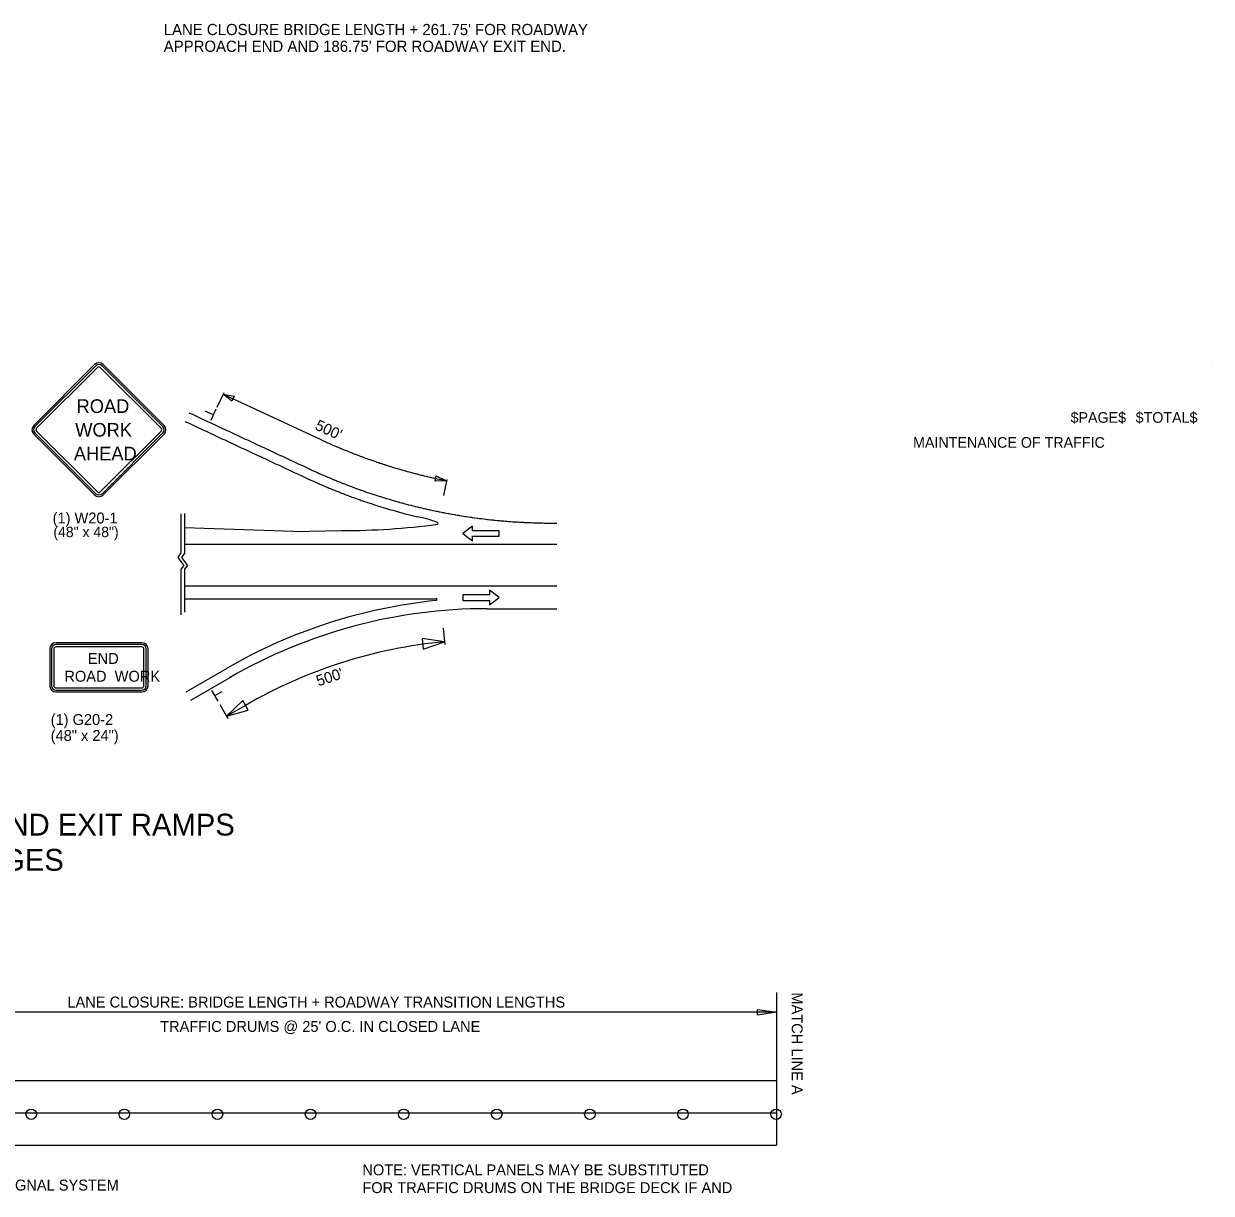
# Model space of a CAD drawing. Extents: x 1930579 to 1939784, y 596179 to 597522.
# Drawn here: x 1938290 to 1938942, y 596879 to 597522 of the extents above; entities that cross this region are included whole.
import ezdxf

# ---------------------------------------------------------------- set-up
doc = ezdxf.new("R2010")
doc.units = 0
for name, color, linetype in [('Default', 7, 'Continuous'), ('P_TC_Signs_Temporary', 7, 'Continuous'), ('R_Annotation', 7, 'Continuous'), ('R_Border', 7, 'Continuous'), ('R_Striping', 7, 'Continuous'), ('S_EDGE_PAVEMENT', 7, 'Continuous'), ('S_SHOULDER', 7, 'Continuous')]:
    doc.layers.add(name, color=color, linetype=linetype)

msp = doc.modelspace()

# ---------------------------------------------------------------- linework, layer by layer
at = {"layer": 'Default'}
for p, q in [((1938399.49, 597319.21), (1938395.68, 597311.05)), ((1938393.76, 597307.15), (1938389.58, 597309.1)), ((1938395.26, 597310.15), (1938392.41, 597304.03)), ((1938522.05, 597271.64), (1938520.29, 597262.81)), ((1938520.16, 597189.93), (1938520.95, 597180.97)), ((1938392.83, 597155.7), (1938396.21, 597149.85)), ((1938394.6, 597152.84), (1938398.59, 597155.14)), ((1938397.32, 597148), (1938401.82, 597140.2)), ((1938411.46, 597147.5), (1938401.07, 597141.5)), ((1938703.26, 596989.79), (1938703.26, 596905.9)), ((1938703.26, 596978.92), (1938258.87, 596978.92)), ((1938692.72, 596977.33), (1938692.72, 596980.49)), ((1938692.72, 596980.49), (1938703.26, 596978.92)), ((1938703.26, 596978.92), (1938692.72, 596977.33)), ((1937601.26, 596941.48), (1938703.26, 596941.48)), ((1937499.1, 596923.69), (1938703.26, 596923.69)), ((1937601.26, 596905.9), (1938703.26, 596905.9))]:
    msp.add_line(p, q, dxfattribs=at)
for points in [[(1938399.17, 597318.53), (1938452.49, 597293.67), (1938452.96, 597293.45), (1938454.06, 597292.94), (1938454.06, 597292.94), (1938455.15, 597292.44), (1938455.64, 597292.22), (1938456.24, 597291.95), (1938457.23, 597291.5), (1938457.34, 597291.46), (1938458.45, 597290.96), (1938458.81, 597290.81), (1938459.54, 597290.48), (1938460.4, 597290.11), (1938460.64, 597290.01), (1938461.76, 597289.53), (1938461.99, 597289.43), (1938462.86, 597289.06), (1938463.59, 597288.75), (1938463.93, 597288.61), (1938463.96, 597288.6), (1938465.09, 597288.13), (1938465.18, 597288.09), (1938466.2, 597287.68), (1938466.79, 597287.43), (1938467.31, 597287.23), (1938468.41, 597286.78), (1938468.42, 597286.78), (1938469.07, 597286.52), (1938469.55, 597286.33), (1938470.01, 597286.15), (1938470.66, 597285.89), (1938471.64, 597285.52), (1938471.78, 597285.46), (1938472.92, 597285.03), (1938473.25, 597284.9), (1938474.04, 597284.6), (1938474.88, 597284.29), (1938475.16, 597284.18), (1938476.3, 597283.76), (1938476.49, 597283.69), (1938477.43, 597283.35), (1938478.13, 597283.09), (1938478.55, 597282.94), (1938479.7, 597282.53), (1938479.75, 597282.51), (1938480.83, 597282.14), (1938481.4, 597281.94), (1938481.96, 597281.74), (1938483.04, 597281.37), (1938483.09, 597281.35), (1938484.24, 597280.96), (1938484.68, 597280.82), (1938485.38, 597280.58), (1938486.33, 597280.27), (1938486.52, 597280.21), (1938487.67, 597279.83), (1938487.97, 597279.74), (1938488.81, 597279.47), (1938489.63, 597279.21), (1938489.95, 597279.1), (1938491.12, 597278.74), (1938491.27, 597278.69), (1938492.26, 597278.39), (1938492.94, 597278.18), (1938493.41, 597278.04), (1938494.57, 597277.69), (1938494.59, 597277.68), (1938495.72, 597277.35), (1938496.26, 597277.19), (1938496.87, 597277.02), (1938497.93, 597276.71), (1938498.02, 597276.68), (1938499.19, 597276.35), (1938499.59, 597276.24), (1938500.34, 597276.03), (1938501.27, 597275.78), (1938501.5, 597275.72), (1938502.67, 597275.4), (1938502.93, 597275.33), (1938503.83, 597275.09), (1938504.62, 597274.88), (1938504.99, 597274.79), (1938506.17, 597274.48), (1938506.29, 597274.45), (1938507.33, 597274.19), (1938507.98, 597274.03), (1938508.49, 597273.9), (1938509.66, 597273.61), (1938510.84, 597273.33), (1938511.34, 597273.21), (1938512, 597273.06), (1938513.04, 597272.81), (1938513.18, 597272.78), (1938513.43, 597272.72), (1938514.35, 597272.51), (1938514.53, 597272.47), (1938514.72, 597272.43), (1938515.52, 597272.25), (1938516.42, 597272.05), (1938516.69, 597271.99), (1938517.88, 597271.74), (1938518.11, 597271.69), (1938519.05, 597271.49), (1938519.81, 597271.33), (1938520.23, 597271.24), (1938521.42, 597271), (1938521.5, 597270.98), (1938521.73, 597270.94), (1938521.73, 597270.94), (1938521.9, 597270.9)], [(1938376.02, 597252.77), (1938376.02, 597231.25), (1938374.36, 597228.78), (1938377.59, 597224.35), (1938375.89, 597222.3), (1938375.88, 597197.28)], [(1938378.06, 597252.97), (1938378.06, 597231.16), (1938376.4, 597228.69), (1938379.64, 597224.26), (1938377.93, 597222.22), (1938377.93, 597198.72)]]:
    msp.add_lwpolyline(points, dxfattribs=at)
for points in [[(1938403.98, 597314.63), (1938399.17, 597318.53), (1938405.24, 597317.35)], [(1938516.32, 597273.55), (1938521.91, 597270.9), (1938515.73, 597270.6)], [(1938509.16, 597178.33), (1938520.82, 597182.46), (1938508.59, 597184.31)], [(1938409.96, 597150.1), (1938401.07, 597141.5), (1938412.96, 597144.9)]]:
    msp.add_lwpolyline(points, close=True, dxfattribs=at)
for centre in [(1938293.74, 596922.85), (1938344.9, 596922.85), (1938396.07, 596922.85), (1938447.23, 596922.85), (1938498.39, 596922.85), (1938549.55, 596922.85), (1938600.72, 596922.85), (1938651.88, 596922.85), (1938703.04, 596922.85)]:
    msp.add_circle(centre, 2.88, dxfattribs=at)
msp.add_arc((1938546.51, 596913.58), 270.11, 95.458, 120.00001, dxfattribs=at)
at = {"layer": 'P_TC_Signs_Temporary'}
for p, q in [((1938295.13, 597301.29), (1938328.54, 597334.71)), ((1938295.79, 597300.63), (1938329.2, 597334.04)), ((1938296.72, 597299.7), (1938330.13, 597333.11)), ((1938331.72, 597333.11), (1938365.13, 597299.7)), ((1938332.65, 597334.04), (1938366.06, 597300.63)), ((1938333.31, 597334.71), (1938366.72, 597301.29)), ((1938330.13, 597264.7), (1938296.72, 597298.11)), ((1938365.13, 597298.11), (1938331.72, 597264.7)), ((1938328.54, 597263.11), (1938295.13, 597296.52)), ((1938329.2, 597263.77), (1938295.79, 597297.18)), ((1938366.06, 597297.18), (1938332.65, 597263.77)), ((1938366.72, 597296.52), (1938333.31, 597263.11)), ((1938354.55, 597181.86), (1938307.3, 597181.86)), ((1938354.55, 597180.92), (1938307.3, 597180.92)), ((1938303.92, 597178.48), (1938303.92, 597158.23)), ((1938304.86, 597178.48), (1938304.86, 597158.23)), ((1938306.17, 597178.48), (1938306.17, 597158.23)), ((1938354.55, 597179.61), (1938307.3, 597179.61)), ((1938355.67, 597158.23), (1938355.67, 597178.48)), ((1938356.99, 597158.23), (1938356.99, 597178.48)), ((1938357.92, 597158.23), (1938357.92, 597178.48)), ((1938307.3, 597157.11), (1938354.55, 597157.11)), ((1938307.3, 597155.79), (1938354.55, 597155.79)), ((1938307.3, 597154.86), (1938354.55, 597154.86))]:
    msp.add_line(p, q, dxfattribs=at)
for centre, radius, start, end in [((1938330.92, 597332.32), 3.38, 45, 135), ((1938330.92, 597332.32), 2.44, 45, 135), ((1938330.92, 597332.32), 1.13, 45, 135), ((1938297.51, 597298.91), 3.37, 135, 225), ((1938297.51, 597298.91), 2.44, 135, 225), ((1938297.51, 597298.91), 1.12, 135, 225), ((1938364.33, 597298.91), 1.12, 315, 45), ((1938364.33, 597298.91), 2.44, 315, 45), ((1938364.33, 597298.91), 3.38, 315, 45), ((1938330.92, 597265.5), 3.38, 225, 315), ((1938330.92, 597265.5), 2.44, 225, 315), ((1938330.92, 597265.5), 1.13, 225, 315), ((1938307.3, 597178.48), 3.38, 90, 180), ((1938307.3, 597178.48), 2.44, 90, 180), ((1938354.55, 597178.48), 3.38, 360, 90), ((1938354.55, 597178.48), 2.44, 360, 90), ((1938307.3, 597178.48), 1.13, 90, 180), ((1938354.55, 597178.48), 1.13, 360, 90), ((1938307.3, 597158.23), 3.38, 180, 270), ((1938307.3, 597158.23), 2.44, 180, 270), ((1938307.3, 597158.23), 1.13, 180, 270), ((1938354.55, 597158.23), 2.44, 270, 360), ((1938354.55, 597158.23), 1.13, 270, 360), ((1938354.55, 597158.23), 3.38, 270, 360)]:
    msp.add_arc(centre, radius, start, end, dxfattribs=at)
at = {"layer": 'R_Border'}
msp.add_line((1938942.12, 597333.4), (1938942.12, 597333.4), dxfattribs=at)
at = {"layer": 'R_Striping'}
for points in [[(1938536.12, 597245.93), (1938530.93, 597241.93), (1938536.12, 597237.93), (1938536.12, 597240.43), (1938550.83, 597240.43), (1938550.83, 597243.43), (1938536.12, 597243.43)], [(1938545.64, 597202.68), (1938550.83, 597206.68), (1938545.64, 597210.68), (1938545.64, 597208.18), (1938530.93, 597208.18), (1938530.93, 597205.18), (1938545.64, 597205.18)]]:
    msp.add_lwpolyline(points, close=True, dxfattribs=at)
at = {"layer": 'S_EDGE_PAVEMENT'}
for p, q in [((1938437.9, 597243.08), (1938378.06, 597245.08)), ((1938437.9, 597243.08), (1938464.18, 597243.53)), ((1938378.2, 597206.08), (1938516.23, 597206.08))]:
    msp.add_line(p, q, dxfattribs=at)
for points in [[(1938378.29, 597303.45), (1938378.57, 597303.32), (1938379.7, 597302.79), (1938380.83, 597302.26), (1938381.96, 597301.73), (1938383.1, 597301.2), (1938384.23, 597300.68), (1938385.36, 597300.15), (1938386.5, 597299.62), (1938387.63, 597299.09), (1938388.76, 597298.56), (1938389.89, 597298.04), (1938391.03, 597297.51), (1938392.16, 597296.98), (1938393.29, 597296.45), (1938394.43, 597295.92), (1938395.56, 597295.39), (1938396.69, 597294.87), (1938397.83, 597294.34), (1938398.96, 597293.81), (1938400.09, 597293.28), (1938401.22, 597292.75), (1938402.36, 597292.22), (1938403.49, 597291.7), (1938404.62, 597291.17), (1938405.76, 597290.64), (1938406.89, 597290.11), (1938408.02, 597289.58), (1938409.15, 597289.05), (1938410.29, 597288.53), (1938411.42, 597288), (1938412.55, 597287.47), (1938413.69, 597286.94), (1938414.82, 597286.41), (1938415.95, 597285.88), (1938417.08, 597285.36), (1938418.22, 597284.83), (1938419.35, 597284.3), (1938420.48, 597283.77), (1938421.62, 597283.24), (1938421.68, 597283.21), (1938422.75, 597282.72), (1938423.88, 597282.19), (1938425.01, 597281.66), (1938425.83, 597281.28), (1938426.15, 597281.13), (1938427.28, 597280.6), (1938428.41, 597280.07), (1938429.55, 597279.55), (1938430.68, 597279.02), (1938431.81, 597278.49), (1938432.94, 597277.96), (1938434.08, 597277.43), (1938435.21, 597276.9), (1938435.55, 597276.74), (1938436.34, 597276.38), (1938437.48, 597275.85), (1938438.61, 597275.32), (1938439.74, 597274.79), (1938440.87, 597274.26), (1938442.01, 597273.73), (1938443.14, 597273.21), (1938444.27, 597272.68), (1938444.92, 597272.38), (1938445.41, 597272.15), (1938446.55, 597271.62), (1938446.56, 597271.62), (1938447.69, 597271.1), (1938448.21, 597270.86), (1938448.84, 597270.58), (1938449.86, 597270.12), (1938449.99, 597270.07), (1938451.14, 597269.56), (1938451.52, 597269.39), (1938452.29, 597269.05), (1938453.18, 597268.67), (1938453.44, 597268.55), (1938454.6, 597268.06), (1938454.84, 597267.95), (1938455.76, 597267.57), (1938456.51, 597267.25), (1938456.86, 597267.1), (1938456.91, 597267.08), (1938458.08, 597266.6), (1938458.19, 597266.55), (1938459.24, 597266.12), (1938459.86, 597265.87), (1938460.4, 597265.65), (1938461.54, 597265.19), (1938461.57, 597265.18), (1938462.24, 597264.91), (1938462.74, 597264.72), (1938463.23, 597264.52), (1938463.91, 597264.26), (1938464.92, 597263.87), (1938465.08, 597263.8), (1938466.26, 597263.35), (1938466.61, 597263.22), (1938467.43, 597262.91), (1938468.3, 597262.58), (1938468.61, 597262.47), (1938469.79, 597262.03), (1938470, 597261.95), (1938470.97, 597261.6), (1938471.71, 597261.33), (1938472.15, 597261.17), (1938473.34, 597260.75), (1938473.41, 597260.72), (1938474.52, 597260.33), (1938475.12, 597260.12), (1938475.71, 597259.92), (1938476.83, 597259.53), (1938476.9, 597259.51), (1938478.09, 597259.11), (1938478.55, 597258.95), (1938479.28, 597258.71), (1938480.27, 597258.38), (1938480.48, 597258.31), (1938481.67, 597257.93), (1938481.99, 597257.82), (1938482.87, 597257.54), (1938483.72, 597257.27), (1938484.07, 597257.16), (1938485.27, 597256.79), (1938485.45, 597256.73), (1938486.47, 597256.42), (1938487.18, 597256.2), (1938487.67, 597256.05), (1938488.88, 597255.69), (1938488.91, 597255.68), (1938490.08, 597255.33), (1938490.65, 597255.17), (1938491.29, 597254.98), (1938492.39, 597254.66), (1938492.5, 597254.63), (1938493.71, 597254.29), (1938494.13, 597254.17), (1938494.92, 597253.95), (1938495.88, 597253.69), (1938496.13, 597253.62), (1938497.35, 597253.29), (1938497.63, 597253.22), (1938498.56, 597252.97), (1938506.16, 597250.98)], [(1938378.87, 597154.95), (1938401.37, 597167.94)]]:
    msp.add_lwpolyline(points, dxfattribs=at)
for centre, radius, start, end in [((1938464.84, 597639.03), 395.5, 269.90557, 277.55497), ((1938496.83, 597197.41), 54.38, 68.27313, 80.11291), ((1938516.77, 597247.46), 0.5, 277.55497, 68.27313), ((1938545.54, 596918.22), 288.35, 95.82454, 119.99999), ((1938516.23, 597205.58), 0.5, 275.82454, 90)]:
    msp.add_arc(centre, radius, start, end, dxfattribs=at)
at = {"layer": 'S_SHOULDER'}
for p, q in [((1938378.09, 597236.08), (1938582.6, 597236.08)), ((1938378.17, 597213.08), (1938582.6, 597213.08)), ((1938544.26, 597200.58), (1938582.6, 597200.58))]:
    msp.add_line(p, q, dxfattribs=at)
for points in [[(1938380.51, 597308.21), (1938380.78, 597308.08), (1938381.92, 597307.55), (1938383.05, 597307.02), (1938384.18, 597306.49), (1938385.32, 597305.96), (1938386.45, 597305.43), (1938387.58, 597304.91), (1938388.72, 597304.38), (1938389.85, 597303.85), (1938390.98, 597303.32), (1938392.11, 597302.79), (1938393.25, 597302.26), (1938394.38, 597301.74), (1938395.51, 597301.21), (1938396.65, 597300.68), (1938397.78, 597300.15), (1938398.91, 597299.62), (1938400.04, 597299.1), (1938401.18, 597298.57), (1938402.31, 597298.04), (1938403.44, 597297.51), (1938404.58, 597296.98), (1938405.71, 597296.45), (1938406.84, 597295.93), (1938407.97, 597295.4), (1938409.11, 597294.87), (1938410.24, 597294.34), (1938411.37, 597293.81), (1938412.51, 597293.28), (1938413.64, 597292.76), (1938414.77, 597292.23), (1938415.9, 597291.7), (1938417.04, 597291.17), (1938418.17, 597290.64), (1938419.3, 597290.11), (1938420.44, 597289.59), (1938421.57, 597289.06), (1938422.7, 597288.53), (1938423.83, 597288), (1938423.9, 597287.97), (1938424.97, 597287.47), (1938426.1, 597286.95), (1938427.23, 597286.42), (1938428.05, 597286.04), (1938428.37, 597285.89), (1938429.5, 597285.36), (1938430.63, 597284.83), (1938431.76, 597284.3), (1938432.9, 597283.78), (1938434.03, 597283.25), (1938435.16, 597282.72), (1938436.3, 597282.19), (1938437.43, 597281.66), (1938437.77, 597281.5), (1938438.56, 597281.13), (1938439.69, 597280.61), (1938440.83, 597280.08), (1938441.96, 597279.55), (1938443.09, 597279.02), (1938444.23, 597278.49), (1938445.36, 597277.96), (1938446.49, 597277.44), (1938447.14, 597277.14), (1938447.62, 597276.91), (1938448.74, 597276.39), (1938448.75, 597276.39), (1938449.87, 597275.88), (1938450.37, 597275.65), (1938450.99, 597275.37), (1938452, 597274.92), (1938452.12, 597274.86), (1938453.25, 597274.36), (1938453.63, 597274.2), (1938454.39, 597273.87), (1938455.26, 597273.49), (1938455.52, 597273.37), (1938456.66, 597272.89), (1938456.9, 597272.78), (1938457.8, 597272.4), (1938458.54, 597272.09), (1938458.89, 597271.95), (1938458.94, 597271.92), (1938460.08, 597271.45), (1938460.19, 597271.41), (1938461.22, 597270.98), (1938461.84, 597270.73), (1938462.37, 597270.52), (1938463.49, 597270.07), (1938463.52, 597270.06), (1938464.17, 597269.8), (1938464.67, 597269.6), (1938465.15, 597269.41), (1938465.82, 597269.15), (1938466.81, 597268.76), (1938466.97, 597268.7), (1938468.13, 597268.26), (1938468.47, 597268.13), (1938469.28, 597267.82), (1938470.14, 597267.5), (1938470.44, 597267.39), (1938471.6, 597266.96), (1938471.81, 597266.88), (1938472.76, 597266.53), (1938473.48, 597266.27), (1938473.93, 597266.11), (1938475.09, 597265.7), (1938475.16, 597265.67), (1938476.26, 597265.29), (1938476.84, 597265.08), (1938477.43, 597264.88), (1938478.53, 597264.5), (1938478.6, 597264.48), (1938479.77, 597264.08), (1938480.22, 597263.93), (1938480.94, 597263.69), (1938481.91, 597263.37), (1938482.11, 597263.3), (1938483.29, 597262.92), (1938483.6, 597262.82), (1938484.47, 597262.54), (1938485.3, 597262.28), (1938485.65, 597262.17), (1938486.83, 597261.8), (1938487, 597261.75), (1938488.01, 597261.43), (1938488.7, 597261.22), (1938489.19, 597261.08), (1938490.38, 597260.72), (1938490.41, 597260.71), (1938491.56, 597260.37), (1938492.12, 597260.21), (1938492.75, 597260.02), (1938493.83, 597259.71), (1938493.94, 597259.68), (1938495.13, 597259.35), (1938495.55, 597259.23), (1938496.32, 597259.01), (1938497.26, 597258.75), (1938497.51, 597258.69), (1938498.71, 597258.36), (1938498.98, 597258.29), (1938499.9, 597258.05), (1938500.71, 597257.83), (1938501.1, 597257.73), (1938502.3, 597257.42), (1938502.43, 597257.39), (1938503.5, 597257.12), (1938504.16, 597256.95), (1938504.7, 597256.82), (1938505.89, 597256.53), (1938505.9, 597256.53), (1938507.1, 597256.24), (1938507.62, 597256.11), (1938508.3, 597255.95), (1938509.36, 597255.71), (1938509.51, 597255.67), (1938509.78, 597255.61), (1938510.71, 597255.4), (1938510.89, 597255.36), (1938511.1, 597255.31), (1938511.92, 597255.13), (1938512.84, 597254.93), (1938513.13, 597254.86), (1938514.34, 597254.6), (1938514.58, 597254.55), (1938515.55, 597254.34), (1938516.32, 597254.18), (1938516.76, 597254.09), (1938517.97, 597253.85), (1938518.07, 597253.83), (1938518.3, 597253.78), (1938518.3, 597253.78), (1938519.18, 597253.6), (1938519.81, 597253.48), (1938520.4, 597253.37), (1938521.56, 597253.14), (1938521.61, 597253.13), (1938522.83, 597252.91), (1938523.16, 597252.84), (1938523.32, 597252.81), (1938524.04, 597252.68), (1938525.07, 597252.5), (1938525.26, 597252.46), (1938526.48, 597252.25), (1938526.82, 597252.19), (1938527.7, 597252.04), (1938528.58, 597251.89), (1938528.92, 597251.84), (1938530.14, 597251.64), (1938530.34, 597251.61), (1938531.36, 597251.44), (1938532.1, 597251.33), (1938532.58, 597251.25), (1938533.8, 597251.07), (1938533.86, 597251.06), (1938535.03, 597250.89), (1938535.62, 597250.8), (1938536.25, 597250.72), (1938537.39, 597250.56), (1938537.48, 597250.54), (1938538.7, 597250.38), (1938539.16, 597250.32), (1938539.21, 597250.31), (1938539.93, 597250.22), (1938540.92, 597250.09), (1938541.15, 597250.06), (1938542.38, 597249.91), (1938542.69, 597249.87), (1938543.61, 597249.77), (1938544.46, 597249.67), (1938544.84, 597249.62), (1938546.07, 597249.49), (1938546.23, 597249.47), (1938547.3, 597249.36), (1938548, 597249.28), (1938548.53, 597249.23), (1938549.76, 597249.11), (1938549.78, 597249.1), (1938550.99, 597248.99), (1938551.55, 597248.94), (1938552.22, 597248.88), (1938553.33, 597248.78), (1938553.45, 597248.77), (1938554.27, 597248.7), (1938554.69, 597248.67), (1938555.1, 597248.63), (1938555.92, 597248.57), (1938556.67, 597248.51), (1938556.88, 597248.5), (1938557.15, 597248.48), (1938558.39, 597248.39), (1938558.66, 597248.37), (1938559.62, 597248.3), (1938560.43, 597248.25), (1938560.85, 597248.23), (1938562.09, 597248.15), (1938562.21, 597248.14), (1938563.32, 597248.08), (1938563.99, 597248.05), (1938564.56, 597248.02), (1938565.77, 597247.96), (1938565.79, 597247.96), (1938567.03, 597247.91), (1938567.55, 597247.88), (1938568.27, 597247.86), (1938569.33, 597247.82), (1938569.5, 597247.81), (1938570.74, 597247.77), (1938571.11, 597247.76), (1938571.97, 597247.74), (1938572.89, 597247.71), (1938573.21, 597247.71), (1938574.45, 597247.68), (1938574.68, 597247.68), (1938575.69, 597247.66), (1938576.94, 597247.64), (1938578.19, 597247.62), (1938579.44, 597247.59), (1938580.69, 597247.57), (1938582.6, 597247.54)], [(1938381.49, 597150.41), (1938403.99, 597163.39)]]:
    msp.add_lwpolyline(points, dxfattribs=at)
msp.add_arc((1938544.26, 596917.48), 283.11, 90, 120.00001, dxfattribs=at)

# ---------------------------------------------------------------- texts
at = {"layer": 'Default'}
for s, height, rotation, p in [("LANE CLOSURE BRIDGE LENGTH + 261.75' FOR ROADWAY ", 6.1396, 360, (1938366.55, 597515.7)), ("APPROACH END AND 186.75' FOR ROADWAY EXIT END.", 6.1396, 360, (1938366.55, 597506.49)), ("500'", 6, 335.23924, (1938449.22, 597299.27)), ("500'", 6, 18.32932, (1938451.54, 597157.89)), ('DETAIL OF ENTRANCE AND EXIT RAMPS', 12, 360, (1938089.94, 597075.96)), ('ALL STAGES', 12, 360, (1938213.53, 597056.62)), ('LANE CLOSURE: BRIDGE LENGTH + ROADWAY TRANSITION LENGTHS', 5.9996, 360, (1938313.6, 596981.49)), ('MATCH LINE A', 5.9996, 270, (1938711.6, 596989.79)), ("TRAFFIC DRUMS @ 25' O.C. IN CLOSED LANE", 5.9996, 360, (1938364.57, 596968.1)), ('PORTABLE TRAFFIC SIGNAL SYSTEM', 5.9996, 360, (1938196.11, 596880.95))]:
    msp.add_text(s, height=height, rotation=rotation, dxfattribs=at).set_placement(p)
at = {"layer": 'P_TC_Signs_Temporary'}
for s, p in [(' ROAD ', (1938315.9, 597308.12)), ('WORK', (1938317.93, 597295.1)), (' AHEAD ', (1938314.38, 597282.07))]:
    msp.add_text(s, height=7.5, dxfattribs=at).set_placement(p)
for s, p in [('END', (1938324.89, 597170.23)), ('ROAD  WORK', (1938311.96, 597160.48))]:
    msp.add_text(s, height=6, rotation=360, dxfattribs=at).set_placement(p)
at = {"layer": 'R_Annotation'}
for s, height, p in [('(1) W20-1', 6, (1938305.52, 597247.41)), ('(48" x 48")', 5.76, (1938305.93, 597239.89)), ('NOTE: VERTICAL PANELS MAY BE SUBSTITUTED', 6, (1938475.69, 596889.3)), ('FOR TRAFFIC DRUMS ON THE BRIDGE DECK IF AND', 6, (1938475.69, 596879.55))]:
    msp.add_text(s, height=height, rotation=360, dxfattribs=at).set_placement(p)
for s, height, p in [('(1) G20-2', 6, (1938304.44, 597136.7)), ('(48" x 24")', 5.9996, (1938304.44, 597127.95))]:
    msp.add_text(s, height=height, dxfattribs=at).set_placement(p)
at = {"layer": 'R_Border'}
for s, height, p in [('$PAGE$', 5.861, (1938864.82, 597302.72)), ('$TOTAL$', 5.861, (1938900.57, 597302.72)), ('MAINTENANCE OF TRAFFIC', 5.862, (1938778.27, 597289)), ('MAINTENANCE OF TRAFFIC', 5.862, (1938778.27, 597289))]:
    msp.add_text(s, height=height, rotation=360, dxfattribs=at).set_placement(p)

doc.saveas('drawing.dxf')
